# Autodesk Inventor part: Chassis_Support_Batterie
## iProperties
Created: 2009-01
Part Number: Chassis_Support_Batterie
Document SubType Name: Sheet Metal
Designer: claivier
Author: claivier
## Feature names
1. Perçage1 [Hole]
2. Perçage2 [Hole]
3. Miroir2 [Mirror]
4. Miroir3 [Mirror]
5. Plaque1
6. Pli1
7. Couper1
